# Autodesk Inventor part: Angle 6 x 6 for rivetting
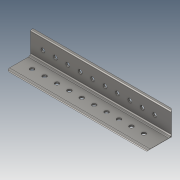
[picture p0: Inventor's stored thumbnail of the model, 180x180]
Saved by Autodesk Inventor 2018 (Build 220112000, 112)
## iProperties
Created: 2018-02
Part Number: Angle 6 x 6 for rivetting
Material: Steel, Mild
Document SubType Name: Modeling
Designer: STK
Density: 7.85 g/cm^3
Appearance: Semi-Polished
Author: STK
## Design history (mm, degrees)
sketch "Sketch1"
  geometry: L1 (11.794, 11.987)-(11.794, 164.387); L2 (21.319, 150.917)-(21.319, 35.8); L3 (150.723, 21.512)-(35.606, 21.512); L4 (164.194, 11.987)-(11.794, 11.987); A1 r 14.287 centre (7.031, 150.917) between (21.319, 150.917) and (11.794, 164.387); A2 r 14.287 centre (35.606, 35.8) between (21.319, 35.8) and (35.606, 21.512); A3 r 14.287 centre (150.723, 7.225) between (164.194, 11.987) and (150.723, 21.512)
  constraints: 8 end point, 6 point on circle, 4 tangent, 3 centre point, 2 equal radius, 1 parallel, 1 perpendicular
  dimensions: "d5" = 14.2875 radius of A2 (derived); "d6" = 152.4 distance from line of L1.end L4 (= d3); "d3" = 152.4 distance from line of L4.start L1 (derived); "d1" = 9.525 distance between parallel lines of L3 L4 (derived); "d0" = 9.525 distance between parallel lines of L2 L1 (= d1)
feature "Angle_equal:1" sketch "Sketch1"
fillet "Fillet1" dims "d7" = 12.7
hole "Hole1" diameter "d10" = 25.4; stored, may be unused: countersink angle "d14" = 82 deg, drill point angle "d16" = 118 deg; dims "d8" = 76.2, "d9" = 76.2, "d11" = 19.05, "d12" = 9.525, "d13" = 6.35, "d15" = 25.4
pattern_linear "Rectangular Pattern1" dims "d19" = 76.2
hole "Hole2" diameter "d22" = 25.4; stored, may be unused: countersink angle "d26" = 82 deg, drill point angle "d28" = 118 deg; dims "d20" = 76.2, "d21" = 76.2, "d23" = 19.05, "d24" = 9.525, "d25" = 6.35, "d27" = 25.4
pattern_linear "Rectangular Pattern2" dims "d31" = 76.2
body "Solid1"
